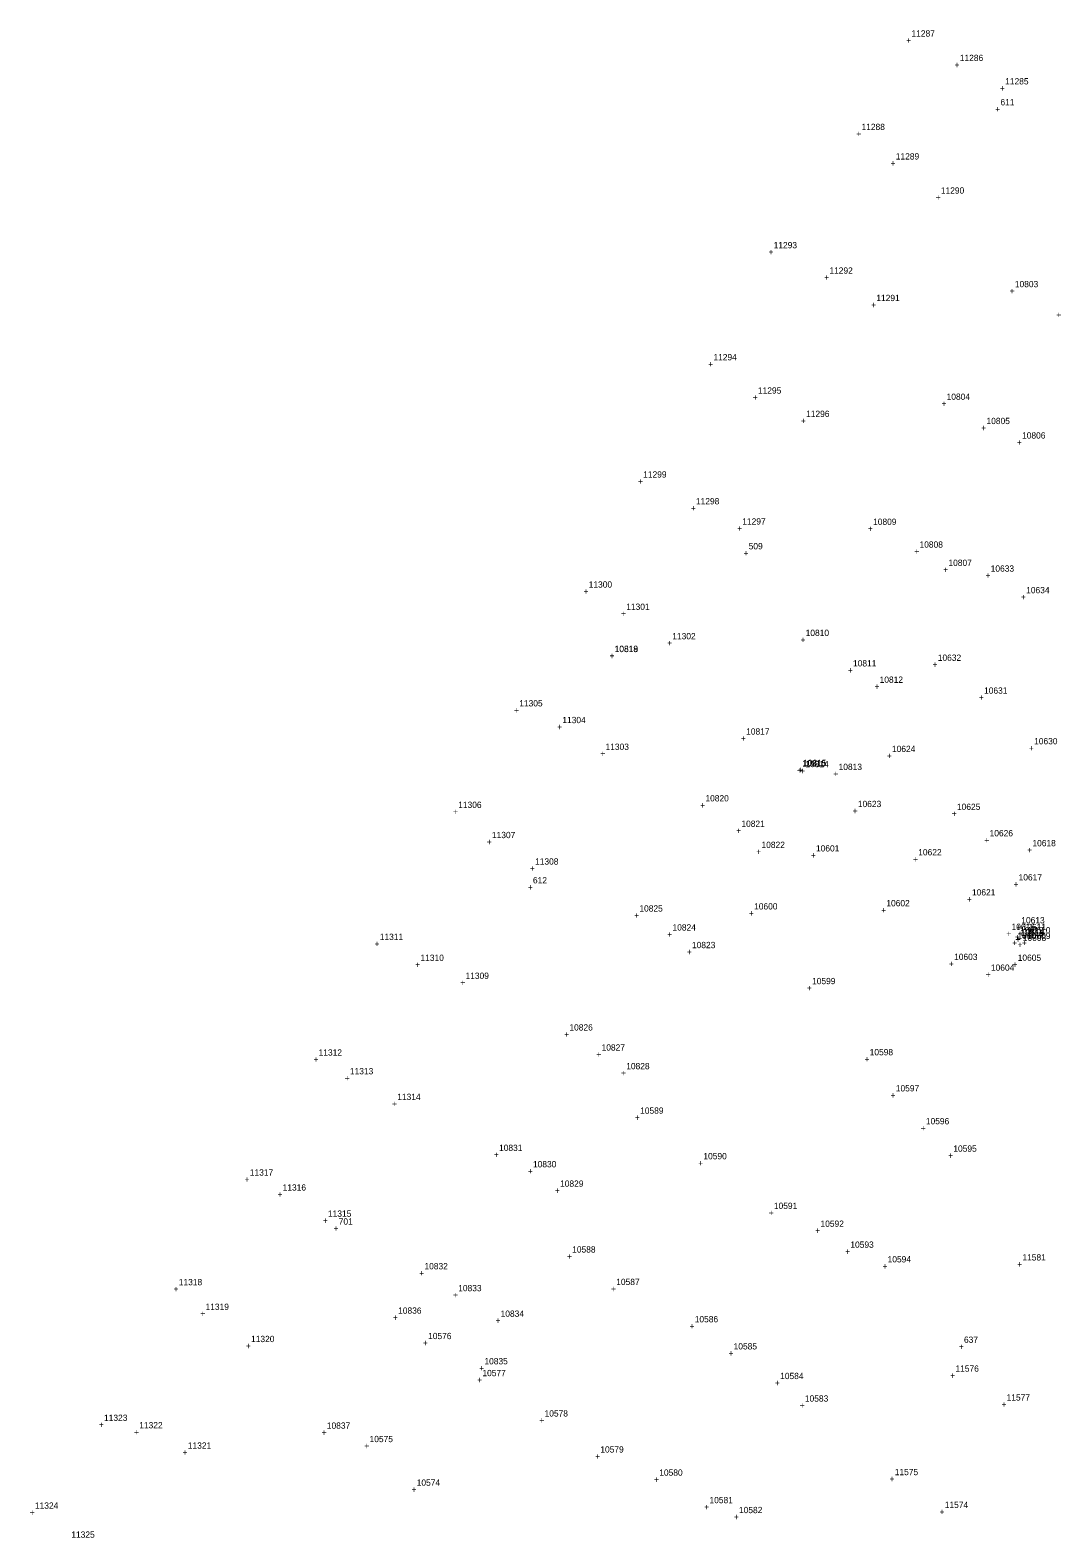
# Model space of a CAD drawing. Extents: x 1160051 to 1162814, y 614604 to 619560.
# Drawn here: x 1161749 to 1162159, y 618329 to 618929 of the extents above; entities that cross this region are included whole.
import ezdxf

# ---------------------------------------------------------------- set-up
doc = ezdxf.new("R2010")
doc.units = 0
for name, color, linetype in [('S_Control_Temp_Traverse', 7, 'Continuous'), ('S_Control_Traverse_Point', 7, 'Continuous'), ('S_Drainage_Culvert_Top', 7, 'Continuous'), ('S_Drainage_Invert', 7, 'Continuous'), ('S_Ground_Elevation', 7, 'Continuous')]:
    doc.layers.add(name, color=color, linetype=linetype)

msp = doc.modelspace()

# ---------------------------------------------------------------- texts
at = {"layer": 'S_Control_Temp_Traverse'}
for s, p in [('611', (1162134.83, 618898.96)), ('+', (1162132.77, 618896.21)), ('+', (1161946.89, 618586.89)), ('612', (1161948.95, 618589.64)), ('637', (1162120.32, 618406.99)), ('+', (1162118.26, 618404.24))]:
    msp.add_text(s, height=2.5, dxfattribs=at).set_placement(p)
at = {"layer": 'S_Control_Traverse_Point'}
for s, p in [('+', (1162032.65, 618719.7)), ('+', (1162032.65, 618719.7)), ('+', (1162032.65, 618719.7)), ('+', (1162032.65, 618719.7)), ('+', (1162032.65, 618719.7)), ('509', (1162034.72, 618722.45)), ('509', (1162034.72, 618722.45)), ('509', (1162034.72, 618722.45)), ('509', (1162034.72, 618722.45)), ('509', (1162034.72, 618722.45)), ('+', (1161869.67, 618451.24)), ('+', (1161869.67, 618451.24)), ('+', (1161869.67, 618451.24)), ('+', (1161869.67, 618451.24)), ('+', (1161869.67, 618451.24)), ('701', (1161871.73, 618453.99)), ('701', (1161871.73, 618453.99)), ('701', (1161871.73, 618453.99)), ('701', (1161871.73, 618453.99)), ('701', (1161871.73, 618453.99))]:
    msp.add_text(s, height=2.5, dxfattribs=at).set_placement(p)
at = {"layer": 'S_Drainage_Culvert_Top'}
for s, p in [('+', (1161979.37, 618678.84)), ('10818', (1161981.43, 618681.59)), ('10816', (1162056, 618636.12)), ('+', (1162053.94, 618633.37)), ('10615', (1162142.95, 618568.79)), ('+', (1162140.89, 618566.04))]:
    msp.add_text(s, height=2.5, dxfattribs=at).set_placement(p)
at = {"layer": 'S_Drainage_Invert'}
for s, p in [('+', (1161979.38, 618678.94)), ('10819', (1161981.44, 618681.69)), ('10815', (1162056.36, 618636.3)), ('+', (1162054.3, 618633.55)), ('10614', (1162142.83, 618568.94)), ('+', (1162140.77, 618566.19))]:
    msp.add_text(s, height=2.5, dxfattribs=at).set_placement(p)
at = {"layer": 'S_Ground_Elevation'}
for s, p in [('+', (1162097.4, 618923.57)), ('11287', (1162099.46, 618926.32)), ('11286', (1162118.66, 618916.57)), ('+', (1162116.59, 618913.82)), ('+', (1162134.63, 618904.52)), ('11285', (1162136.7, 618907.27)), ('+', (1162077.53, 618886.4)), ('11288', (1162079.59, 618889.15)), ('+', (1162091.14, 618874.68)), ('11289', (1162093.21, 618877.43)), ('11290', (1162111.13, 618863.86)), ('+', (1162109.07, 618861.11)), ('+', (1162042.59, 618839.39)), ('11293', (1162044.65, 618842.14)), ('11292', (1162066.81, 618832.03)), ('+', (1162064.75, 618829.28)), ('10803', (1162140.55, 618826.66)), ('11291', (1162085.47, 618821.14)), ('+', (1162138.49, 618823.91)), ('+', (1162083.41, 618818.39)), ('+', (1162157.05, 618814.46)), ('11294', (1162020.7, 618797.6)), ('+', (1162018.64, 618794.85)), ('11295', (1162038.4, 618784.35)), ('+', (1162036.34, 618781.6)), ('+', (1162111.36, 618779.13)), ('10804', (1162113.42, 618781.88)), ('+', (1162055.49, 618772.33)), ('11296', (1162057.55, 618775.08)), ('10805', (1162129.28, 618772.24)), ('+', (1162127.22, 618769.49)), ('10806', (1162143.41, 618766.49)), ('+', (1162141.34, 618763.74)), ('11299', (1161992.78, 618750.98)), ('+', (1161990.72, 618748.23)), ('+', (1162011.7, 618737.58)), ('11298', (1162013.76, 618740.33)), ('11297', (1162032.18, 618732.31)), ('10809', (1162084.19, 618732.17)), ('+', (1162030.12, 618729.56)), ('+', (1162082.13, 618729.42)), ('+', (1162100.59, 618720.36)), ('10808', (1162102.65, 618723.11)), ('+', (1162112.09, 618713.11)), ('10807', (1162114.15, 618715.86)), ('10633', (1162130.94, 618713.57)), ('11300', (1161971.12, 618707.23)), ('+', (1162128.88, 618710.82)), ('+', (1161969.06, 618704.48)), ('+', (1162142.98, 618702.25)), ('10634', (1162145.05, 618705)), ('+', (1161983.98, 618695.64)), ('11301', (1161986.04, 618698.39)), ('10810', (1162057.38, 618688)), ('+', (1162002.29, 618683.95)), ('11302', (1162004.35, 618686.7)), ('+', (1162055.32, 618685.25)), ('10632', (1162109.9, 618678.13)), ('+', (1162074.14, 618673.15)), ('10811', (1162076.2, 618675.9)), ('+', (1162107.84, 618675.38)), ('+', (1162084.72, 618666.63)), ('10812', (1162086.78, 618669.38)), ('10631', (1162128.3, 618665.06)), ('11305', (1161943.5, 618660)), ('+', (1162126.24, 618662.31)), ('+', (1161941.44, 618657.25)), ('11304', (1161960.64, 618653.35)), ('+', (1161958.58, 618650.6)), ('10817', (1162033.72, 618648.8)), ('11303', (1161977.81, 618642.73)), ('+', (1162031.66, 618646.05)), ('10624', (1162091.69, 618641.87)), ('+', (1162146.15, 618642.2)), ('10630', (1162148.21, 618644.95)), ('+', (1161975.75, 618639.98)), ('10814', (1162057.25, 618635.85)), ('10813', (1162070.47, 618634.72)), ('+', (1162089.63, 618639.12)), ('+', (1162055.18, 618633.1)), ('+', (1162068.4, 618631.97)), ('10820', (1162017.52, 618622.24)), ('+', (1161917.17, 618616.89)), ('11306', (1161919.23, 618619.64)), ('+', (1162015.46, 618619.49)), ('+', (1162076.07, 618617.23)), ('10623', (1162078.13, 618619.98)), ('10625', (1162117.53, 618618.86)), ('10821', (1162031.83, 618612.12)), ('+', (1162115.46, 618616.11)), ('+', (1161930.58, 618604.89)), ('11307', (1161932.64, 618607.64)), ('+', (1162029.77, 618609.37)), ('+', (1162128.44, 618605.61)), ('10626', (1162130.51, 618608.36)), ('10618', (1162147.53, 618604.41)), ('+', (1162037.76, 618600.99)), ('10822', (1162039.82, 618603.74)), ('+', (1162059.42, 618599.59)), ('10601', (1162061.48, 618602.34)), ('10622', (1162102.13, 618600.78)), ('+', (1162145.47, 618601.66)), ('+', (1161947.73, 618594.37)), ('11308', (1161949.79, 618597.12)), ('+', (1162100.07, 618598.03)), ('+', (1162139.98, 618588.07)), ('10617', (1162142.04, 618590.82)), ('10602', (1162089.46, 618580.54)), ('+', (1162121.45, 618582.1)), ('10621', (1162123.51, 618584.85)), ('+', (1161989.21, 618575.7)), ('10825', (1161991.27, 618578.45)), ('+', (1162034.82, 618576.53)), ('10600', (1162036.88, 618579.28)), ('+', (1162087.39, 618577.79)), ('10824', (1162004.44, 618570.9)), ('10616', (1162139.23, 618571.14)), ('+', (1162141.05, 618571)), ('10612', (1162142.66, 618569.82)), ('10613', (1162143.11, 618573.75)), ('10611', (1162143.64, 618571.08)), ('10610', (1162145.4, 618569.78)), ('+', (1161885.99, 618564.41)), ('11311', (1161888.05, 618567.16)), ('+', (1162002.38, 618568.15)), ('10823', (1162012.17, 618563.9)), ('+', (1162137.17, 618568.39)), ('+', (1162139.51, 618564.8)), ('+', (1162140.6, 618567.07)), ('+', (1162141.58, 618568.33)), ('+', (1162141.66, 618564.02)), ('10607', (1162141.57, 618567.55)), ('+', (1162143.33, 618564.78)), ('+', (1162143.34, 618567.03)), ('10608', (1162143.72, 618566.77)), ('10609', (1162145.39, 618567.53)), ('11310', (1161904.24, 618558.84)), ('+', (1162010.11, 618561.15)), ('10603', (1162116.39, 618559.2)), ('10605', (1162141.68, 618558.86)), ('+', (1161902.18, 618556.09)), ('11309', (1161922.15, 618551.69)), ('+', (1162114.33, 618556.45)), ('+', (1162128.97, 618552.16)), ('10604', (1162131.03, 618554.91)), ('+', (1162139.62, 618556.11)), ('+', (1161920.09, 618548.94)), ('+', (1162057.86, 618546.83)), ('10599', (1162059.92, 618549.58)), ('+', (1161961.37, 618528.41)), ('10826', (1161963.44, 618531.16)), ('11312', (1161863.74, 618521.2)), ('10827', (1161976.24, 618523.18)), ('10598', (1162082.83, 618521.3)), ('+', (1161861.68, 618518.45)), ('+', (1161974.18, 618520.43)), ('10828', (1161986.04, 618515.77)), ('+', (1162080.77, 618518.55)), ('+', (1161874.11, 618511)), ('11313', (1161876.17, 618513.75)), ('+', (1161983.98, 618513.02)), ('11314', (1161895, 618503.54)), ('+', (1162091.16, 618504.2)), ('10597', (1162093.22, 618506.95)), ('+', (1161892.93, 618500.79)), ('10589', (1161991.57, 618498.07)), ('+', (1161989.51, 618495.32)), ('+', (1162103.11, 618491.13)), ('10596', (1162105.17, 618493.88)), ('+', (1161933.41, 618480.54)), ('10831', (1161935.47, 618483.29)), ('10590', (1162016.71, 618479.97)), ('+', (1162114.03, 618480.22)), ('10595', (1162116.09, 618482.97)), ('11317', (1161836.39, 618473.48)), ('+', (1161946.89, 618474.02)), ('10830', (1161948.96, 618476.77)), ('+', (1162014.65, 618477.22)), ('+', (1161834.33, 618470.73)), ('11316', (1161849.43, 618467.52)), ('10829', (1161959.73, 618469.04)), ('+', (1161847.36, 618464.77)), ('+', (1161957.67, 618466.29)), ('10591', (1162044.74, 618460.22)), ('11315', (1161867.45, 618457.12)), ('+', (1162042.68, 618457.47)), ('+', (1161865.39, 618454.37)), ('+', (1162061.22, 618450.37)), ('10592', (1162063.28, 618453.12)), ('10588', (1161964.55, 618442.88)), ('10593', (1162075.15, 618444.79)), ('10832', (1161905.82, 618436.22)), ('+', (1161962.49, 618440.13)), ('+', (1162073.09, 618442.04)), ('10594', (1162089.96, 618438.97)), ('+', (1162141.5, 618436.99)), ('11581', (1162143.56, 618439.74)), ('+', (1161903.76, 618433.47)), ('+', (1162087.9, 618436.22)), ('+', (1161806.08, 618427.14)), ('11318', (1161808.14, 618429.89)), ('+', (1161917.17, 618424.77)), ('10833', (1161919.23, 618427.52)), ('+', (1161980, 618427.22)), ('10587', (1161982.06, 618429.97)), ('11319', (1161818.78, 618420.1)), ('10836', (1161895.35, 618418.56)), ('+', (1161816.72, 618417.35)), ('+', (1161893.29, 618415.81)), ('+', (1161934.03, 618414.59)), ('10834', (1161936.09, 618417.34)), ('10586', (1162013.27, 618415.15)), ('11320', (1161836.87, 618407.29)), ('10576', (1161907.27, 618408.47)), ('+', (1162011.2, 618412.4)), ('+', (1161834.81, 618404.54)), ('+', (1161905.21, 618405.72)), ('+', (1162026.67, 618401.62)), ('10585', (1162028.73, 618404.37)), ('+', (1161927.59, 618395.7)), ('10835', (1161929.65, 618398.45)), ('11576', (1162116.94, 618395.51)), ('+', (1161926.8, 618391)), ('10577', (1161928.86, 618393.75)), ('+', (1162045.18, 618389.83)), ('10584', (1162047.24, 618392.58)), ('+', (1162114.88, 618392.76)), ('10583', (1162057.07, 618383.62)), ('11577', (1162137.27, 618384.06)), ('10578', (1161953.57, 618377.71)), ('+', (1162055.01, 618380.87)), ('+', (1162135.21, 618381.31)), ('+', (1161776.35, 618373.22)), ('11323', (1161778.41, 618375.97)), ('11322', (1161792.42, 618373.01)), ('10837', (1161867.01, 618372.84)), ('+', (1161951.51, 618374.96)), ('+', (1161790.36, 618370.26)), ('11321', (1161811.74, 618364.92)), ('+', (1161864.95, 618370.09)), ('+', (1161881.93, 618364.77)), ('10575', (1161883.99, 618367.52)), ('+', (1161809.68, 618362.17)), ('+', (1161973.67, 618360.63)), ('10579', (1161975.74, 618363.38)), ('10580', (1161999.17, 618354.17)), ('11575', (1162092.81, 618354.39)), ('+', (1161900.67, 618347.43)), ('10574', (1161902.73, 618350.18)), ('+', (1161997.11, 618351.42)), ('+', (1162090.75, 618351.64)), ('11324', (1161750.94, 618341.05)), ('10581', (1162019.14, 618343.24)), ('11574', (1162112.69, 618341.34)), ('+', (1161748.88, 618338.3)), ('+', (1162017.08, 618340.49)), ('+', (1162028.8, 618336.54)), ('10582', (1162030.86, 618339.29)), ('+', (1162110.63, 618338.59)), ('11325', (1161765.42, 618329.51))]:
    msp.add_text(s, height=2.5, dxfattribs=at).set_placement(p)

doc.saveas('drawing.dxf')
